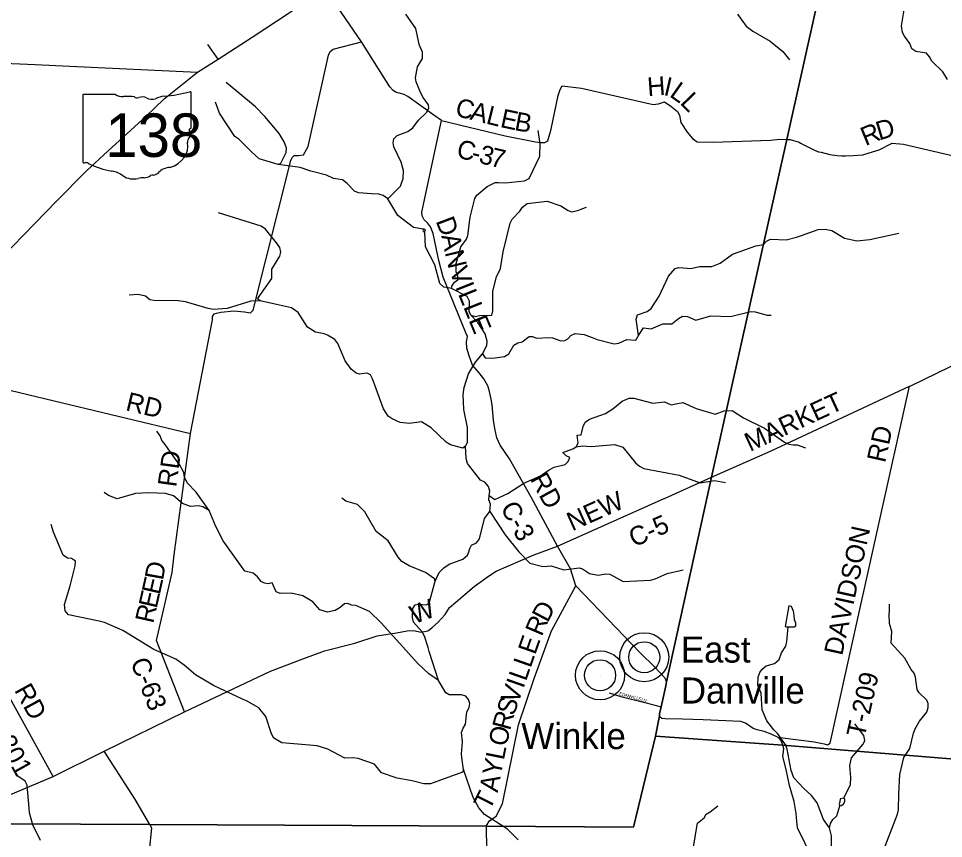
# Model space of a CAD drawing. Extents: x 1525783 to 1900577, y 218250 to 627376.
# Drawn here: x 1612574 to 1627391, y 405833 to 418967 of the extents above; entities that cross this region are included whole.
import ezdxf

# ---------------------------------------------------------------- set-up
doc = ezdxf.new("R2010")
doc.units = 0
for name, color, linetype in [('GM_X_County_Road', 7, 'Continuous'), ('GM_X_County_Road_Text', 7, 'Continuous'), ('GM_X_Minor_Lake', 7, 'Continuous'), ('GM_X_Minor_River', 7, 'Continuous'), ('GM_X_State_Location', 7, 'Continuous'), ('GM_X_State_Route', 7, 'Continuous'), ('GM_X_State_Shield', 7, 'Continuous'), ('GM_X_Township', 7, 'Continuous'), ('GM_X_Township_Road', 7, 'Continuous'), ('GM_X_Township_Road_Text', 7, 'Continuous'), ('GM_X_Township_Subdivision', 7, 'Continuous'), ('GM_X_Township_Subdivision_Text', 7, 'Continuous'), ('GM_X_Unincorporated', 7, 'Continuous'), ('GM_X_Unincorporated_Location', 7, 'Continuous'), ('GM_X_Unincorporated_Text', 7, 'Continuous')]:
    doc.layers.add(name, color=color, linetype=linetype)

msp = doc.modelspace()

# ---------------------------------------------------------------- linework, layer by layer
at = {"layer": 'GM_X_County_Road'}
for points in [[(1621504, 409878), (1621417, 410151), (1621209, 410516), (1620786, 411302), (1620437, 411916), (1620291, 412135), (1620236, 412251), (1620206, 412398), (1620181, 412535), (1620174, 412658), (1620162, 412778), (1620146, 412869), (1620116, 413016), (1620092, 413083), (1620030, 413193), (1619955, 413294), (1619844, 413413), (1619794, 413565), (1619755, 413688), (1619751, 413789), (1619764, 413875), (1619737, 413930), (1619378, 414822), (1619309, 415089), (1619241, 415394), (1619216, 415523), (1619171, 415628), (1619123, 415694), (1619072, 415742), (1619038, 415807), (1619033, 415865), (1619348, 417333), (1619228, 417418), (1618810, 417715), (1618754, 417748), (1618671, 417769), (1618612, 417786), (1618568, 417818), (1618520, 417875), (1618070, 418592), (1617485, 419446)], [(1615231, 407863), (1614785, 409007), (1615036, 410091), (1615068, 410379), (1615331, 412320), (1615679, 414141), (1615683, 414193), (1615708, 414234), (1615746, 414249), (1615815, 414263), (1616024, 414285), (1616192, 414267), (1616292, 414252), (1616335, 414295), (1616938, 416691), (1616959, 416738), (1616990, 416775), (1617059, 416773), (1617141, 416785), (1617215, 416919), (1617539, 418377), (1617565, 418441), (1617615, 418474), (1618070, 418592)], [(1619348, 417333), (1620367, 417085), (1620853, 416993), (1620943, 416980), (1621007, 416983), (1621052, 417007), (1621107, 417192), (1621220, 417731), (1621251, 417828), (1621284, 417887), (1621592, 417851), (1622738, 417587), (1622826, 417601), (1622923, 417632), (1623026, 417565), (1623128, 417480), (1623160, 417421), (1623185, 417302), (1623285, 417147), (1623373, 417046), (1623443, 416990), (1623700, 416985), (1624621, 417019), (1624768, 417033), (1624883, 417031), (1624936, 417030), (1625077, 416984), (1625101, 416972), (1625115, 416965), (1625121, 416962)], [(1625121, 416962), (1625325, 416857), (1625389, 416834), (1625434, 416824), (1625573, 416789), (1625686, 416772), (1625757, 416765), (1625823, 416765), (1625946, 416770), (1626098, 416784), (1626252, 416833), (1626360, 416864), (1626570, 416969), (1626752, 416952), (1627872, 416690), (1629309, 416366), (1630641, 416048), (1631793, 415765)], [(1622920, 411280), (1623677, 411619), (1624629, 412044), (1626847, 413077), (1626866, 413086), (1628742, 413996)], [(1621209, 410516), (1622919, 411280), (1622920, 411280)], [(1619729, 409744), (1619730, 409745), (1619875, 409867), (1620103, 410035), (1620227, 410114), (1620819, 410369), (1621209, 410516)], [(1620088, 405591), (1620077, 405762), (1620068, 405919), (1620072, 406029), (1620073, 406040), (1620120, 406114), (1620224, 406191), (1620328, 406387), (1620583, 407653), (1620833, 408394), (1621112, 409159), (1621504, 409878)], [(1622534, 408805), (1621504, 409878)], [(1619132, 409161), (1619141, 409163), (1619202, 409212), (1619292, 409293), (1619407, 409419), (1619479, 409532), (1619577, 409616), (1619729, 409744)], [(1611256, 406038), (1611342, 406074), (1613127, 406826), (1613947, 407230), (1615231, 407863), (1616608, 408515), (1617145, 408715), (1617473, 408841), (1617964, 408964), (1618317, 409077), (1618631, 409129), (1618798, 409160), (1618899, 409164), (1619022, 409136), (1619131, 409161), (1619132, 409161)], [(1622950, 408355), (1622945, 408375), (1622925, 408407), (1622761, 408584), (1622539, 408800), (1622534, 408805)], [(1624824, 407309), (1624820, 407328), (1624791, 407400), (1624743, 407453), (1624628, 407506), (1624516, 407545), (1624405, 407575), (1624342, 407597), (1624219, 407680), (1624144, 407709), (1623903, 407720), (1623542, 407734), (1623209, 407743), (1622931, 407749), (1622881, 407753), (1622853, 407775), (1622841, 407796), (1622843, 407828), (1622871, 407940), (1622942, 408277), (1622952, 408343), (1622950, 408355)], [(1625409, 405275), (1625055, 406003), (1625043, 406106), (1625029, 406236), (1624997, 406428), (1624926, 406684), (1624870, 406939), (1624816, 407145), (1624833, 407267), (1624824, 407309)]]:
    msp.add_lwpolyline(points, dxfattribs=at)
at = {"layer": 'GM_X_Minor_Lake'}
for points in [[(1619081, 415551), (1619085, 415565), (1619091, 415577), (1619085, 415587), (1619071, 415593), (1619061, 415591), (1619055, 415581), (1619053, 415571), (1619055, 415561), (1619067, 415549)], [(1619067, 415549), (1619081, 415551)], [(1624853, 409227), (1624874, 409224), (1624901, 409224), (1624949, 409225), (1624999, 409226), (1625027, 409240), (1625028, 409282), (1625007, 409334), (1624998, 409408), (1624989, 409475), (1624958, 409547), (1624916, 409558)], [(1624916, 409558), (1624853, 409227)], [(1625737, 406466), (1625730, 406422), (1625721, 406390), (1625729, 406354), (1625755, 406364), (1625789, 406387), (1625810, 406425), (1625809, 406463), (1625795, 406479)], [(1625795, 406479), (1625737, 406466)]]:
    msp.add_lwpolyline(points, dxfattribs=at)
at = {"layer": 'GM_X_Minor_River'}
for points in [[(1627454, 417990), (1627383, 418114), (1627204, 418284), (1627165, 418351), (1627118, 418409), (1626950, 418440), (1626883, 418481), (1626850, 418569), (1626764, 418684), (1626734, 418741), (1626716, 418851), (1626765, 419139), (1626768, 419193)], [(1618488, 416081), (1618691, 416283), (1618738, 416402), (1618740, 416531), (1618703, 416667), (1618585, 416911), (1618576, 416975), (1618588, 417039), (1618639, 417091), (1618810, 417158), (1618888, 417218), (1618980, 417338), (1619107, 417463), (1619146, 417531), (1619143, 417583), (1619058, 417704), (1619019, 417771), (1618946, 417950), (1618935, 418014), (1618963, 418192), (1619047, 418327), (1619044, 418427), (1618991, 418548), (1618982, 418606), (1618937, 418807), (1618780, 419035)], [(1624093, 419036), (1624229, 418846), (1624338, 418764), (1624617, 418604), (1624815, 418440), (1624925, 418306)], [(1616731, 416627), (1616774, 416650), (1616860, 416820), (1616867, 416892), (1616830, 416992), (1616752, 417127), (1616520, 417399), (1616370, 417553), (1615899, 417944)], [(1619061, 415591), (1618902, 415619), (1618648, 415813), (1618488, 416081), (1618417, 416134), (1618347, 416155), (1618228, 416161), (1618018, 416177), (1617958, 416200), (1617840, 416324), (1617763, 416381), (1617621, 416405), (1617506, 416457), (1617259, 416520), (1617084, 416582), (1616731, 416627), (1616427, 416717), (1616299, 416835), (1616230, 416908), (1616105, 417036), (1616040, 417077), (1615793, 417448), (1615732, 417627)], [(1619508, 414640), (1619517, 414682), (1619558, 414743), (1619614, 414783), (1619611, 414839), (1619584, 414907), (1619583, 415041), (1619659, 415309), (1619748, 415434), (1619769, 415492), (1619807, 415784), (1619884, 416083), (1619915, 416139), (1620081, 416275), (1620207, 416339), (1620261, 416340), (1620377, 416333), (1620681, 416369), (1620754, 416404), (1620924, 416762), (1620929, 416966), (1620899, 417171)], [(1619818, 414217), (1619894, 414192), (1619960, 414209), (1620158, 414213), (1620171, 414283), (1620171, 414599), (1620232, 414831), (1620297, 414962), (1620339, 415232), (1620451, 415689), (1620481, 415751), (1620605, 415883), (1620648, 415945), (1620722, 416004), (1621044, 416040), (1621259, 415967), (1621378, 415891), (1621438, 415872), (1621550, 415897), (1621600, 415916), (1621672, 415943)], [(1616444, 414444), (1616404, 414476), (1616634, 414802), (1616634, 414950), (1616758, 415161), (1616775, 415226), (1616762, 415297), (1616707, 415372), (1616528, 415594), (1616459, 415643), (1615777, 415856)], [(1619734, 412115), (1619764, 412177), (1619765, 412415), (1619709, 412707), (1619698, 412945), (1619714, 413057), (1619780, 413274), (1619895, 413461), (1620006, 413598), (1620078, 413729), (1620079, 413799), (1620050, 413914), (1619931, 414096), (1619818, 414217), (1619795, 414274), (1619799, 414442), (1619760, 414512), (1619508, 414640), (1619456, 414651), (1619387, 414666), (1619324, 414720), (1619244, 415020), (1619093, 415310), (1619081, 415551)], [(1620006, 413598), (1620047, 413531), (1620171, 413524), (1620357, 413553), (1620426, 413598), (1620509, 413734), (1620572, 413771), (1620640, 413788), (1620753, 413873), (1620805, 413872), (1620870, 413847), (1621068, 413856), (1621126, 413852), (1621259, 413806), (1621325, 413811), (1621376, 413836), (1621420, 413888), (1621489, 413921), (1621636, 413903), (1621763, 413859), (1621843, 413828), (1622116, 413755), (1622188, 413766), (1622318, 413826), (1622464, 413816), (1622507, 413888), (1622470, 414150), (1622491, 414220), (1622642, 414274), (1622706, 414324), (1622839, 414518), (1622985, 414841), (1623092, 414961), (1623144, 414981), (1623224, 414972), (1623344, 414964), (1623484, 414994), (1623678, 414996), (1623816, 415048), (1624012, 415190), (1624120, 415232), (1624387, 415327), (1624507, 415349), (1624558, 415403), (1624620, 415432), (1624870, 415423), (1625038, 415465), (1625114, 415492), (1625385, 415586), (1625497, 415595), (1625605, 415573), (1625805, 415451), (1626002, 415404), (1626212, 415429), (1626675, 415527)], [(1619734, 412115), (1619689, 412086), (1619492, 412141), (1619427, 412182), (1619184, 412411), (1619031, 412505), (1618835, 412480), (1618690, 412494), (1618558, 412553), (1618497, 412600), (1618421, 412717), (1618247, 413194), (1618214, 413257), (1618160, 413288), (1618034, 413269), (1617983, 413288), (1617902, 413353), (1617809, 413485), (1617687, 413763), (1617642, 413825), (1617523, 413897), (1617469, 413916), (1617332, 413945), (1617205, 414025), (1617052, 414256), (1616945, 414333), (1616706, 414386), (1616444, 414444), (1616294, 414442), (1615917, 414322), (1615697, 414305), (1615613, 414322), (1615251, 414429), (1615133, 414447), (1614746, 414452), (1614678, 414463), (1614607, 414520), (1614489, 414545), (1614349, 414535)], [(1622507, 413888), (1622586, 414011), (1622708, 413999), (1622895, 414077), (1623041, 414079), (1623144, 414164), (1623212, 414199), (1623288, 414194), (1623423, 414136), (1623664, 414205), (1623981, 414193), (1624304, 414273), (1624375, 414268), (1624569, 414215), (1624630, 414216)], [(1621506, 412108), (1621540, 412164), (1621521, 412294), (1621589, 412301), (1621617, 412433), (1621650, 412499), (1621723, 412550), (1621977, 412641), (1622096, 412713), (1622244, 412838), (1622358, 412888), (1622430, 412885), (1622735, 412805), (1622923, 412827), (1623030, 412779), (1623102, 412794), (1623214, 412817), (1623427, 412718), (1623735, 412628), (1623878, 412682), (1624007, 412686), (1624188, 412570), (1624523, 412405), (1624844, 412183), (1624911, 412150), (1624981, 412141), (1625049, 412140), (1625182, 412088)], [(1614905, 412165), (1614869, 412209), (1614857, 412242), (1614844, 412284), (1614791, 412355)], [(1619304, 408365), (1619149, 408472), (1618972, 408637), (1618384, 409289), (1618197, 409471), (1617980, 409567), (1617910, 409572), (1617849, 409597), (1617797, 409590), (1617727, 409531), (1617649, 409484), (1617524, 409458), (1617399, 409498), (1617289, 409622), (1617130, 409719), (1616940, 409760), (1616764, 409757), (1616701, 409784), (1616635, 409929), (1616571, 409914), (1616517, 409921), (1616459, 409952), (1616402, 410023), (1616333, 410083), (1616200, 410115), (1615850, 410601), (1615735, 410833), (1615626, 411088), (1615418, 411378), (1615277, 411532), (1615232, 411621), (1615223, 411693), (1615153, 411821), (1615116, 411871), (1614905, 412165)], [(1620113, 411328), (1620122, 411398), (1620103, 411472), (1620042, 411539), (1619975, 411571), (1619765, 411842), (1619746, 411917), (1619734, 412115)], [(1620113, 411328), (1620204, 411262), (1620414, 411361), (1620667, 411525), (1620937, 411643), (1621073, 411739), (1621152, 411783), (1621333, 411822), (1621381, 411874), (1621403, 411935), (1621349, 411960), (1621294, 412017), (1621453, 412073), (1621506, 412108)], [(1621506, 412108), (1621609, 412125), (1621747, 412111), (1622121, 412146), (1622256, 412100)], [(1622256, 412100), (1622460, 411852), (1622519, 411799), (1622593, 411762), (1623158, 411652), (1623494, 411528), (1623723, 411565), (1623897, 411536)], [(1615626, 411088), (1615524, 411145), (1615455, 411161), (1615330, 411153), (1615203, 411201), (1615059, 411321), (1614929, 411360), (1614663, 411368), (1614447, 411358), (1614155, 411274), (1614016, 411329), (1613944, 411374)], [(1619246, 409956), (1619237, 409992), (1619095, 410093), (1618830, 410203), (1618713, 410271), (1618654, 410337), (1618495, 410600), (1618303, 410749), (1618124, 411066), (1618002, 411185), (1617819, 411236), (1617751, 411283)], [(1620580, 405810), (1620408, 405985), (1620040, 406218), (1619950, 406325), (1619856, 406491), (1619704, 406940), (1619675, 407129), (1619672, 407191), (1619685, 407379), (1619672, 407530), (1619695, 407601), (1619736, 407663), (1619753, 407861), (1619795, 407932), (1619802, 407998), (1619783, 408061), (1619742, 408115), (1619668, 408135), (1619472, 408136), (1619420, 408167), (1619304, 408365), (1619153, 408826), (1619134, 408895), (1619079, 409074), (1619038, 409142), (1618899, 409297), (1618886, 409373), (1618893, 409515), (1618930, 409577), (1618986, 409586), (1619104, 409574), (1619154, 409601), (1619246, 409956), (1619311, 410095), (1619388, 410170), (1619475, 410225), (1619693, 410307), (1619766, 410370), (1619787, 410424), (1619804, 410476), (1619833, 410531), (1619908, 410568), (1619961, 410631), (1620038, 410957), (1620122, 411069), (1620134, 411189), (1620107, 411256), (1620113, 411328)], [(1620122, 411069), (1620368, 410695), (1620588, 410423), (1620765, 410242), (1620972, 410188), (1621109, 410200), (1621308, 410138), (1621553, 410170), (1621609, 410155), (1621719, 410080), (1621861, 410053), (1621982, 410073), (1622044, 410066), (1622262, 409948), (1622697, 409971), (1622771, 409990), (1622963, 410077), (1623220, 410137)], [(1613865, 409314), (1613373, 409416), (1613322, 409479), (1613313, 409583), (1613399, 409878), (1613482, 410203), (1613485, 410274), (1613424, 410316), (1613358, 410325), (1613288, 410370), (1613137, 410739), (1613097, 410862)], [(1626402, 405570), (1626654, 406221), (1626673, 406292), (1626675, 406549), (1626692, 406857), (1626755, 407128), (1626852, 407277), (1626912, 407518), (1626937, 407588), (1627005, 407711), (1627122, 407859), (1627145, 407929), (1627144, 407993), (1627123, 408047), (1627001, 408168), (1626968, 408222), (1626945, 408417), (1626920, 408481), (1626871, 408538), (1626772, 408720), (1626554, 408962), (1626565, 409150), (1626525, 409275), (1626522, 409421), (1626525, 409479), (1626527, 409587)], [(1619704, 406940), (1619685, 406897), (1619173, 406707), (1619065, 406711), (1618878, 406756), (1618640, 406800), (1618389, 406884), (1618278, 407026), (1618015, 407114), (1617937, 407124), (1617803, 407118), (1617529, 407265), (1617356, 407318), (1616984, 407352), (1616794, 407365), (1616665, 407441), (1616624, 407510), (1616535, 407788), (1616421, 407924), (1616228, 408037), (1616171, 408060), (1615696, 408282), (1615407, 408457), (1615227, 408607), (1615094, 408705), (1614743, 408861), (1614243, 409162), (1613951, 409293), (1613865, 409314)], [(1625597, 405677), (1625597, 405877), (1625567, 406004), (1625471, 406136), (1625369, 406402), (1625277, 406522), (1625155, 406632), (1624996, 406807), (1624953, 406920), (1624889, 407265), (1624862, 407334), (1624739, 407508), (1624672, 407575), (1624561, 407719), (1624489, 407893), (1624468, 408161), (1624416, 408288), (1624422, 408418), (1624448, 408490), (1624485, 408548), (1624548, 408599), (1624686, 408636), (1624757, 408701), (1624797, 408805), (1624865, 408914), (1624881, 408990), (1624901, 409224)], [(1625795, 406479), (1625901, 406700), (1625909, 406812), (1625890, 407000), (1625916, 407124), (1626102, 407343), (1626129, 407401), (1626116, 407485), (1625969, 407672)], [(1612927, 405802), (1612805, 406054), (1612751, 406245), (1612746, 406317), (1612713, 406690), (1612678, 406753), (1612533, 406853)], [(1621618, 404093), (1621618, 403990), (1621776, 403978), (1621983, 403998), (1622115, 404034), (1622317, 404141), (1622366, 404194), (1622416, 404308), (1622550, 404496), (1622690, 404622), (1622914, 404866), (1622964, 404938), (1623024, 405083), (1623169, 405261), (1623237, 405370), (1623380, 405670), (1623449, 406079), (1623557, 406164), (1623588, 406221), (1623653, 406262), (1623777, 406356)], [(1625567, 406004), (1625580, 406072), (1625617, 406140), (1625680, 406197), (1625729, 406354)]]:
    msp.add_lwpolyline(points, dxfattribs=at)
at = {"layer": 'GM_X_State_Route'}
for points in [[(1615443, 418107), (1615771, 418317), (1616315, 418667), (1616912, 419057), (1617485, 419446), (1617757, 419632), (1617966, 419751), (1618379, 420034), (1619089, 420519), (1619877, 421085), (1620724, 421697), (1621940, 422579), (1623166, 423382), (1623858, 423784), (1623917, 423818), (1626807, 425668), (1628096, 426444)], [(1602048, 418923), (1602207, 418917), (1603014, 418877), (1604113, 418795), (1605023, 418727), (1605595, 418682), (1606001, 418653), (1606117, 418641), (1606594, 418594), (1607594, 418486), (1607944, 418455), (1608586, 418427), (1609883, 418364), (1611598, 418285), (1612839, 418232), (1613398, 418205), (1615443, 418107)], [(1605382, 408178), (1605535, 408330), (1605581, 408375), (1606035, 408824), (1607003, 409758), (1607587, 410373), (1608196, 411110), (1608269, 411183), (1609514, 412424), (1610377, 413202), (1610549, 413372), (1611185, 413993), (1611955, 414781), (1613181, 416039), (1613652, 416518), (1614010, 416850), (1614613, 417396), (1614907, 417682), (1615443, 418107)]]:
    msp.add_lwpolyline(points, dxfattribs=at)
at = {"layer": 'GM_X_State_Shield'}
for p, q in [((1613602, 417732), (1613602, 416675)), ((1614128, 417750), (1613619, 417750)), ((1615342, 417224), (1615342, 417776)), ((1615342, 417224), (1615342, 417224))]:
    msp.add_line(p, q, dxfattribs=at)
for centre, major_axis, start_param, end_param in [((1613622, 417734), (20.2, 0), 1.712693, 3.28349), ((1614250, 417873), (196, 0), 4.042523, 4.731795), ((1614315, 417157), (702, 0), 1.404758, 1.657858), ((1614474, 417740), (56.4, 0), 3.836095, 5.185415), ((1614557, 417618), (117, 0), 0.950623, 2.079405), ((1614957, 417427), (371, 0), 1.699011, 2.107814), ((1614722, 419191), (1845, 0), 4.814394, 5.042369), ((1615323, 417779), (19.4, 0), 6.141152, 7.989035), ((1614708, 417785), (141, 0), 4.081561, 5.145723), ((1615337, 417183), (30, 0), 1.883978, 3.671073), ((1615147, 417113), (180, 0), 5.934695, 6.695948), ((1615321, 417221), (20.7, 0), 5.05454, 6.418171), ((1614825, 416922), (462, 0), 5.101752, 6.440018), ((1615411, 416992), (131, 0), 2.387724, 3.262537), ((1613622, 416673), (20.3, 0), 3.00124, 4.508301), ((1613625, 416781), (155, 0), 4.665946, 4.897461), ((1613657, 416614), (56, 0), 0.519207, 1.627899), ((1614363, 417564), (1333, 0), 4.195997, 4.488961), ((1613966, 416201), (417, 0), 0.823519, 1.323587), ((1615020, 416379), (253, 0), 1.647645, 2.488434), ((1614417, 416609), (265, 0), 4.026481, 4.996735), ((1614570, 416244), (217, 0), 1.495662, 1.94098), ((1614589, 416530), (141, 0), 4.691044, 5.507374), ((1614717, 416428), (39.7, 0), 1.147584, 2.315152), ((1614700, 416573), (149, 0), 4.937069, 5.64225)]:
    msp.add_ellipse(centre, major_axis=major_axis, ratio=0.8, start_param=start_param, end_param=end_param, dxfattribs=at)
at = {"layer": 'GM_X_Township'}
for points in [[(1627027, 435051), (1627134, 430332), (1627200, 427431), (1627041, 426719), (1626807, 425668), (1626127, 422617), (1624883, 417031), (1623677, 411619), (1622952, 408343), (1622942, 408277), (1622871, 407940), (1622843, 407828), (1622841, 407796), (1622778, 407474), (1622426, 406016), (1620072, 406029), (1614677, 406057), (1611342, 406074)], [(1628024, 407066), (1624820, 407328), (1622778, 407474), (1622841, 407796), (1622843, 407828), (1622871, 407940), (1622942, 408277), (1622952, 408343), (1623677, 411619), (1624883, 417031), (1626127, 422617), (1626807, 425668), (1627041, 426719), (1627200, 427431), (1627134, 430332), (1627027, 435051)], [(1611342, 406074), (1614677, 406057), (1620072, 406029), (1622426, 406016), (1622778, 407474), (1624820, 407328), (1628024, 407066), (1632117, 406770), (1632138, 406667), (1632121, 406517), (1631982, 406356), (1631927, 406313), (1631827, 406210), (1631784, 406179), (1631741, 406115), (1631750, 406091), (1631888, 406080), (1631970, 406057), (1632136, 405991), (1632170, 405973), (1632227, 405919), (1632267, 405903), (1632429, 405914), (1632719, 405833)]]:
    msp.add_lwpolyline(points, dxfattribs=at)
at = {"layer": 'GM_X_Township_Road'}
for points in [[(1610549, 413372), (1610825, 413370), (1611277, 413292), (1613013, 412877), (1615331, 412320)], [(1613127, 406826), (1612173, 408551), (1611990, 408859), (1611069, 412223), (1611195, 412930), (1611277, 413292)], [(1624743, 407453), (1624820, 407447), (1625320, 407383), (1625480, 407348), (1625535, 407335), (1625576, 407360), (1625856, 408615), (1626847, 413077)], [(1614671, 405634), (1614710, 406000), (1614677, 406057), (1614437, 406467), (1613947, 407230)]]:
    msp.add_lwpolyline(points, dxfattribs=at)
at = {"layer": 'GM_X_Township_Subdivision'}
for points in [[(1615771, 418317), (1615607, 418550)], [(1622035, 408164), (1622225, 408109), (1622626, 408005), (1622871, 407940)]]:
    msp.add_lwpolyline(points, dxfattribs=at)
at = {"layer": 'GM_X_Unincorporated'}
for centre, radius in [((1622598, 408736), 393), ((1622598, 408736), 249), ((1621889, 408447), 393), ((1621889, 408447), 249)]:
    msp.add_circle(centre, radius, dxfattribs=at)
at = {"layer": 'GM_X_Unincorporated_Location'}
for p, q in [((1622598, 408736), (1622598, 408736)), ((1621889, 408447), (1621889, 408447))]:
    msp.add_line(p, q, dxfattribs=at)

# ---------------------------------------------------------------- texts
at = {"layer": 'GM_X_County_Road_Text'}
for s, rotation, p in [('H', 4.2624, (1622656, 417722)), ('I', 347.1537, (1622895, 417743)), ('L', 324.8656, (1622987, 417728)), ('L', 314.5106, (1623160, 417608)), ('C', 345.8932, (1619553, 417411)), ('A', 345.897, (1619792, 417351)), ('L', 346.1663, (1620050, 417286)), ('E', 347.8126, (1620277, 417231)), ('B', 349.6253, (1620506, 417181)), ('R', 22.3783, (1626141, 416922)), ('D', 16.6174, (1626361, 417013)), ('C', 345.8771, (1619573, 416747)), ('3', 346.0459, (1619933, 416657)), ('7', 346.7503, (1620116, 416611)), ('-', 345.917, (1619812, 416687)), ('D', 290.7931, (1619254, 415724)), ('A', 282.1222, (1619344, 415488)), ('N', 283.6763, (1619401, 415222)), ('V', 289.6905, (1619474, 414932)), ('I', 291.7149, (1619567, 414673)), ('L', 291.756, (1619612, 414558)), ('L', 291.7702, (1619696, 414350)), ('E', 292.4513, (1619780, 414138)), ('MARKET', 24.7653, (1624292, 412024)), ('RD', 82.0799, (1615099, 411452)), ('RD', 298.7676, (1620762, 411591)), ('NEW', 24.1453, (1621443, 410752)), ('C-3', 298.3589, (1620287, 411134)), ('C-5', 24.1032, (1622434, 410494)), ('D', 79.7397, (1614888, 409958)), ('E', 77.2654, (1614836, 409725)), ('E', 77.1572, (1614786, 409506)), ('R', 77.1556, (1614731, 409266)), ('W', 20.8214, (1618915, 409263)), ('D', 62.213, (1621049, 409279)), ('R', 66.8667, (1620955, 409058)), ('E', 70.6177, (1620850, 408764)), ('C-63', 291.4818, (1614362, 408662)), ('L', 70.6653, (1620776, 408553)), ('L', 70.6653, (1620702, 408341)), ('I', 70.6628, (1620661, 408225)), ('V', 70.6677, (1620573, 407975)), ('S', 71.3712, (1620509, 407785)), ('R', 74.806, (1620446, 407551)), ('O', 78.1307, (1620393, 407297)), ('L', 78.5736, (1620348, 407078)), ('Y', 78.5754, (1620296, 406819)), ('A', 79.6812, (1620249, 406561)), ('T', 63.2797, (1620119, 406272))]:
    msp.add_text(s, height=300, rotation=rotation, dxfattribs=at).set_placement(p)
at = {"layer": 'GM_X_State_Location'}
for s in ['s', 'r']:
    msp.add_text(s, height=1, dxfattribs=at).set_placement((1614452, 417133))
msp.add_text('138', height=1, rotation=0, dxfattribs=at).set_placement((1614099, 417061))
at = {"layer": 'GM_X_State_Shield'}
msp.add_text('138', height=696.1, dxfattribs=at).set_placement((1613964, 416750))
at = {"layer": 'GM_X_Township_Road_Text'}
for s, rotation, p in [('RD', 346.5615, (1614276, 412695)), ('RD', 77.525, (1626454, 411840)), ('DAVIDSON', 77.4998, (1625767, 408751)), ('T-209', 77.258, (1626126, 407436)), ('RD', 298.7673, (1612500, 408210)), ('T-201', 299.3271, (1612039, 407718))]:
    msp.add_text(s, height=300, rotation=rotation, dxfattribs=at).set_placement(p)
at = {"layer": 'GM_X_Township_Subdivision_Text'}
for s, rotation, p in [('E', 344.7676, (1622193, 408132)), ('D', 344.7842, (1622240, 408119)), ('A', 344.7889, (1622282, 408108)), ('N', 344.7631, (1622325, 408096)), ('V', 344.7889, (1622367, 408084)), ('I', 344.7391, (1622410, 408073)), ('L', 344.7829, (1622431, 408067)), ('L', 344.7984, (1622465, 408058)), ('E', 344.7676, (1622499, 408049)), ('L', 344.7829, (1622546, 408036)), ('N', 345.1821, (1622580, 408027))]:
    msp.add_text(s, height=50, rotation=rotation, dxfattribs=at).set_placement(p)
at = {"layer": 'GM_X_Unincorporated_Text'}
for s, p in [('East', (1623185, 408651)), ('Danville', (1623185, 407995)), ('Winkle', (1620629, 407265))]:
    msp.add_text(s, height=417, rotation=0, dxfattribs=at).set_placement(p)

doc.saveas('drawing.dxf')
